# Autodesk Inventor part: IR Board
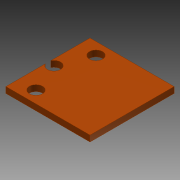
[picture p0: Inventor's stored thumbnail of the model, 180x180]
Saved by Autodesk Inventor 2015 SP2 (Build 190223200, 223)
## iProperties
Created: 2015-09
Part Number: IR Board
Material: Phenolharz
Document SubType Name: Modeling
Designer: rYan
Mass: 0.266145 g
Surface Area: 4.48 cm^2
Volume: 0.192858 cm^3
Density: 1.38 g/cm^3
Appearance: Glatt - hellorange
Author: rYan
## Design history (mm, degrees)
sketch "Skizze1"
  geometry: L1 (7, 7)-(-7, 7); L2 (-7, 7)-(-7, -7); L3 (-7, -7)-(7, -7); L4 (7, -7)-(7, 7); L5 (7, 7)-(-7, -7); L6 (-7, 7)-(7, -7); 1 further point
  constraints: 12 end point, 2 midpoint, 2 parallel, 1 horizontal, 1 perpendicular
  dimensions: "d0" = 14 distance of L3.end L2.end; "d1" = 14 distance of L2.end L1.end
extrude "Extrusion1" new body sketch "Skizze1" distance "d2" = 1; taper "d3" = 0 deg
sketch "Skizze2"
  geometry: L1 (0, 9.8)-(0, -9.8) reference; L2 (-9.8, 0)-(9.8, 0) reference; 2 further points
  constraints: 1 point on line
  dimensions: "d4" = 6 distance from line of L1 point (-6, 0)
hole "Bohrung1" sketch "Skizze2" at (-6, 0) diameter "d5" = 2.2; stored, may be unused: countersink angle "d9" = 90 deg, drill point angle "d11" = 118 deg; dims "d6" = 6, "d7" = 4, "d8" = 2, "d10" = 8
sketch "Skizze3"
  geometry: L1 (-4, 5)-(-4, -5); L2 (0, 9.8)-(0, -9.8) reference; L3 (-9.8, 0)-(9.8, 0) reference; 1 further point
  constraints: 2 end point, 1 symmetric about line, 1 vertical
  dimensions: "d12" = 4 distance between parallel lines of L2 L1; "d13" = 10 distance of L1.start L1.end
hole "Bohrung2" sketch "Skizze3" at (-4, 5), (-4, -5) diameter "d14" = 2.2; stored, may be unused: countersink angle "d18" = 90 deg, drill point angle "d20" = 118 deg; dims "d15" = 6, "d16" = 4, "d17" = 2, "d19" = 8
node "Volumenkörper1"
